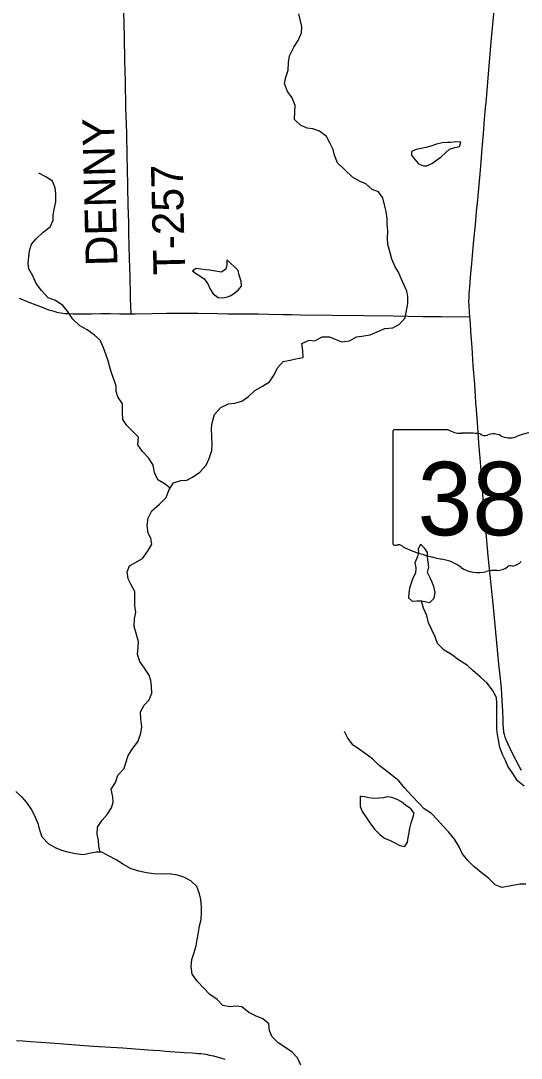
# Model space of a CAD drawing. Extents: x 1442749 to 1756758, y 235267 to 677782.
# Drawn here: x 1557097 to 1561837, y 528893 to 538726 of the extents above; entities that cross this region are included whole.
import ezdxf

# ---------------------------------------------------------------- set-up
doc = ezdxf.new("R2010")
doc.units = 0
for name, color, linetype in [('GM_X_County_Road', 7, 'Continuous'), ('GM_X_Minor_Lake', 7, 'Continuous'), ('GM_X_Minor_River', 7, 'Continuous'), ('GM_X_State_Location', 7, 'Continuous'), ('GM_X_State_Route', 7, 'Continuous'), ('GM_X_State_Shield', 7, 'Continuous'), ('GM_X_Township_Road', 7, 'Continuous'), ('GM_X_Township_Road_Text', 7, 'Continuous')]:
    doc.layers.add(name, color=color, linetype=linetype)

msp = doc.modelspace()

# ---------------------------------------------------------------- linework, layer by layer
at = {"layer": 'GM_X_County_Road'}
msp.add_lwpolyline([(1557056.5, 529060.7), (1557115.2, 529056.9), (1557189.4, 529052.1), (1557287.6, 529044.7), (1557376.8, 529037.8), (1557465.4, 529031.6), (1557656.3, 529017.7), (1557785.8, 529008.4), (1557948.9, 528998), (1558064.5, 528990.6), (1558181.6, 528982.5), (1558265.8, 528976.2), (1558301.4, 528973.2), (1558352, 528969.7), (1558413.1, 528965.2), (1558466.4, 528961.2), (1558556.9, 528954.9), (1558648.5, 528948.5), (1558721.2, 528943.4), (1558754.4, 528940.7), (1558777.5, 528938.8), (1558803.5, 528936.1), (1558829.4, 528933), (1558848.7, 528929.9), (1558884.3, 528923.4), (1558921.4, 528914.9), (1558953.8, 528905.9), (1558988.9, 528896.3), (1559030.3, 528884.3)], dxfattribs=at)
at = {"layer": 'GM_X_Minor_Lake'}
for points in [[(1561259.3, 537554.3), (1561266.6, 537574), (1561216.6, 537576.9), (1561170.5, 537571.9), (1561138.5, 537570.5), (1561088.5, 537569.5), (1561034.2, 537556.5), (1560979.8, 537537.6), (1560933.5, 537524.5), (1560889.3, 537515.3), (1560843.1, 537504.2), (1560798.7, 537487.1), (1560798, 537453), (1560818, 537426)], [(1560818, 537426), (1560864.3, 537369.6), (1560911.9, 537350.6), (1560942, 537352), (1560990.4, 537373.1), (1561079.8, 537437.4), (1561118.5, 537472.7), (1561159.3, 537510), (1561207.5, 537523), (1561251.8, 537534.2), (1561259.3, 537554.3)], [(1559080.3, 536118.9), (1559110.6, 536136.4), (1559157.4, 536171.5), (1559188.2, 536210.9), (1559183.1, 536257.1), (1559164.3, 536313.6), (1559155.2, 536357.8), (1559123.9, 536390.5), (1559084.6, 536429.3), (1559047.3, 536460.1), (1559048.3, 536412), (1559039.4, 536370.2), (1559007.5, 536349.8)], [(1559007.5, 536349.8), (1558996.8, 536343), (1558941, 536352.1), (1558889.2, 536363.1), (1558849.3, 536365.9), (1558803.4, 536372.8), (1558757.5, 536377.8), (1558725.1, 536356.3), (1558760.4, 536325.6), (1558794.1, 536306.9), (1558833.5, 536278.1), (1558868.6, 536233.3), (1558891.5, 536182.8), (1558918.6, 536136.2), (1558967.9, 536103.2), (1559009.9, 536100.3), (1559056.1, 536109.4), (1559080.3, 536118.9)], [(1560895.4, 533752.1), (1560884.6, 533763.3), (1560859.7, 533719.8), (1560862.8, 533677.6), (1560849.9, 533633.8), (1560829, 533588.2), (1560838, 533539.9), (1560835, 533489.9), (1560810, 533442.3), (1560795, 533394.5), (1560780.1, 533348.7), (1560771.1, 533302.8), (1560768.2, 533254.8), (1560805.6, 533226), (1560847.6, 533227.2), (1560893.6, 533226.3)], [(1560893.6, 533226.3), (1560971.3, 533212.7), (1561012.2, 533254), (1561021.3, 533305.9), (1561008.4, 533362.2), (1560991.4, 533410.6), (1560970.2, 533451.1), (1560949.1, 533495.6), (1560962.1, 533545.4), (1560955.2, 533595.7), (1560948.1, 533641.9), (1560949, 533685.9), (1560923.7, 533722.5), (1560895.4, 533752.1)], [(1560324.6, 531373.1), (1560311.7, 531374.6), (1560312.7, 531326.5), (1560311.7, 531278.4), (1560330.8, 531232), (1560365.8, 531181.2), (1560396.8, 531132.5), (1560420.2, 531102), (1560449.3, 531061.3), (1560496.4, 531012.3), (1560543.7, 530979.3), (1560597.2, 530956.2), (1560638.8, 530933.4), (1560686.3, 530910.4), (1560736.1, 530899.4), (1560761, 530941), (1560765.9, 530984.9)], [(1560765.9, 530984.9), (1560774.8, 531032.8), (1560781.7, 531074.8), (1560794.7, 531122.6), (1560811.7, 531172.3), (1560822.5, 531214.2), (1560791.4, 531256.9), (1560742.1, 531289.9), (1560702.7, 531322.8), (1560661.2, 531345.6), (1560611.6, 531364.7), (1560567.7, 531369.5), (1560533.5, 531362.2), (1560487.4, 531359.1), (1560441.3, 531354), (1560393.4, 531361), (1560351.6, 531369.8), (1560324.6, 531373.1)]]:
    msp.add_lwpolyline(points, dxfattribs=at)
at = {"layer": 'GM_X_Minor_River'}
for points in [[(1560762.6, 536113.6), (1560753.6, 536163.9), (1560728.8, 536220.5), (1560698.2, 536289.2), (1560673.2, 536341.8), (1560642.3, 536394.4), (1560611.7, 536465.2), (1560593.2, 536537.7), (1560572.6, 536606.2), (1560569.8, 536666.3), (1560575.2, 536732.3), (1560568.6, 536800.6), (1560567.7, 536852.7), (1560557, 536919), (1560546, 536969.3), (1560525.6, 537045.8), (1560486.8, 537104.7), (1560425.2, 537127.9), (1560366.3, 537179.2), (1560310.8, 537202.3), (1560239.5, 537241.8), (1560167, 537313.3), (1560098.3, 537378.8), (1560067.8, 537451.5), (1560054.9, 537505.8), (1560024.2, 537568.6), (1559993.4, 537629.3), (1559926.4, 537680.7), (1559862.8, 537700), (1559809, 537707), (1559745.5, 537736.3), (1559690.6, 537789.5), (1559694.1, 537863.6), (1559695.3, 537921.6), (1559666.8, 537994.3), (1559622, 538055.3), (1559595.6, 538131.9), (1559606.8, 538189.8), (1559628.2, 538257.5), (1559631.7, 538329.5), (1559641, 538393.4), (1559684.7, 538476.7), (1559725.9, 538538), (1559757.5, 538611.5), (1559758.7, 538671.6), (1559731.2, 538792.3)], [(1558511.6, 534297.1), (1558463.7, 534334.2), (1558396.5, 534373.6), (1558363.9, 534444.4), (1558351.3, 534512.8), (1558310.6, 534579.7), (1558249.9, 534643), (1558205.2, 534706), (1558212.7, 534777.9), (1558161.7, 534829), (1558100.9, 534888.3), (1558064.1, 534945.2), (1558061.6, 535019.3), (1558061.1, 535093.5), (1558016.4, 535160.5), (1557999.5, 535210.9), (1558000.5, 535260.9), (1557983.5, 535311.3), (1557955.1, 535390), (1557940.2, 535442.4), (1557925.4, 535502.8), (1557906.5, 535557.3), (1557881.9, 535625.9), (1557849.4, 535698.6), (1557794.4, 535745.8), (1557725.4, 535797.2), (1557656.1, 535832.7), (1557591.4, 535896.1), (1557541, 535973.2), (1557494, 536026.2), (1557427, 536073.6), (1557355.5, 536101.1), (1557294.9, 536168.4), (1557244.3, 536235.5), (1557211.7, 536308.2), (1557173.1, 536373.1), (1557168.1, 536425.3), (1557173.4, 536489.3), (1557178.6, 536545.3), (1557199.9, 536608.9), (1557242.9, 536660.2), (1557310.2, 536720.9), (1557375.3, 536771.8), (1557404.6, 536835.3), (1557403.6, 536885.4), (1557412.7, 536937.3), (1557430.1, 537009), (1557427.7, 537085.2), (1557422.9, 537143.4), (1557396.1, 537204), (1557333, 537247.3), (1557269.7, 537282.7)], [(1557850.3, 530845.8), (1557835.6, 530902.8), (1557834.7, 530958.9), (1557821.8, 531015.3), (1557825.2, 531081.3), (1557866.6, 531150.6), (1557915.7, 531201.7), (1557955, 531267.1), (1557972.1, 531318.8), (1557969.1, 531369), (1557952.5, 531441.4), (1557993.9, 531506.7), (1558015.3, 531576.4), (1558076.6, 531637.3), (1558093.7, 531691.1), (1558115.1, 531762.8), (1558154.4, 531824.1), (1558209.9, 531897.1), (1558233.5, 531974.8), (1558242.7, 532032.7), (1558234.2, 532109), (1558229.6, 532175.2), (1558266.9, 532238.6), (1558313.9, 532289.8), (1558337.2, 532351.4), (1558336.6, 532419.5), (1558329.7, 532473.8), (1558312.7, 532524.2), (1558268, 532589.2), (1558225.3, 532652.1), (1558202.7, 532720.7), (1558210.1, 532790.7), (1558213.1, 532840.7), (1558194.5, 532909.2), (1558170.1, 532985.8), (1558173.6, 533059.8), (1558186.8, 533117.7), (1558178.1, 533182), (1558177.4, 533248.1), (1558176.8, 533316.2), (1558140.2, 533385), (1558113.3, 533437.7), (1558104.6, 533502), (1558127.8, 533559.6), (1558178.4, 533588.6), (1558249.2, 533629.3), (1558302.8, 533704.4), (1558338, 533763.8), (1558329.1, 533818), (1558302.2, 533872.7), (1558295.6, 533942.9), (1558305.1, 534012.8), (1558338.5, 534082.3), (1558409.8, 534145), (1558475, 534205.8), (1558502.6, 534283.4), (1558543.9, 534346.7), (1558612.4, 534369.4), (1558670.5, 534372.2), (1558723.1, 534401.2), (1558794.1, 534447.9), (1558853.4, 534512.8), (1558880.8, 534578.4), (1558908.3, 534652), (1558911.4, 534708), (1558902.5, 534860.4), (1558909.7, 534916.4), (1558933.3, 534994), (1558992.6, 535061), (1559063.3, 535093.6), (1559125.5, 535102.4), (1559191.9, 535121.1), (1559252.8, 535166), (1559314, 535222.9), (1559386.9, 535263.5), (1559451.7, 535302.3), (1559497.1, 535369.5), (1559528.4, 535437), (1559581.7, 535496), (1559647.9, 535508.7), (1559702.2, 535521.7), (1559770.5, 535534.3), (1559769.8, 535598.4), (1559759.2, 535666.8), (1559829.8, 535697.4), (1559881.8, 535692.4), (1559950.5, 535729.1), (1560022.6, 535729.7), (1560074.1, 535708.6), (1560137.6, 535683.3), (1560209.8, 535691.9), (1560276.6, 535728.6), (1560328.7, 535735.6), (1560405, 535748.1), (1560473.6, 535776.8), (1560546.3, 535809.4), (1560620.4, 535813.9), (1560683.2, 535848.8), (1560736.4, 535909.8), (1560763.2, 536045.5), (1560762.6, 536113.6)], [(1561864, 531470.1), (1561803, 531521.3), (1561756.5, 531592.4), (1561711.8, 531659.4), (1561688.9, 531713.9), (1561661.9, 531764.6), (1561635.4, 531837.2), (1561622.9, 531909.6), (1561611.9, 531959.9), (1561605, 532012.1), (1561606, 532064.2), (1561605.4, 532130.3), (1561606.5, 532184.4), (1561606, 532256.5), (1561603.1, 532312.7), (1561566.5, 532381.5), (1561515.9, 532448.6), (1561451, 532504), (1561378.3, 532567.5), (1561327.2, 532614.7), (1561242.3, 532668.4), (1561177.3, 532717.8), (1561108.1, 532759.2), (1561043.4, 532822.6), (1561020.7, 532885.2), (1560990.1, 532953.9), (1560957.4, 533018.7), (1560942.8, 533089.1), (1560910.2, 533157.8), (1560893.6, 533226.3)], [(1561881.1, 530544.1), (1561827, 530541.2), (1561774.8, 530532.2), (1561724.7, 530523.2), (1561654.4, 530512.5), (1561588.9, 530535.9), (1561528.2, 530599.2), (1561459.2, 530652.6), (1561388.4, 530710.1), (1561331.5, 530767.4), (1561278.9, 530832.5), (1561248.2, 530897.2), (1561205.6, 530970.2), (1561149.1, 531039.4), (1561096.2, 531096.6), (1561045.3, 531151.7), (1560986.6, 531213), (1560917.4, 531256.4), (1560870.5, 531307.4), (1560801.9, 531380.9), (1560735.4, 531452.4), (1560678.8, 531521.6), (1560613.8, 531571), (1560542.9, 531628.5), (1560491.7, 531667.5), (1560427, 531728.9), (1560358, 531782.4), (1560304.7, 531817.5), (1560245.6, 531858.8), (1560194.9, 531925.9), (1560164.2, 531990.6)], [(1559749.7, 528827.2), (1559717.2, 528897.9), (1559668.2, 528951), (1559599.1, 528996.4), (1559534, 529037.8), (1559477.1, 529095), (1559454.3, 529151.6), (1559445.6, 529217.9), (1559388.6, 529267.1), (1559321.1, 529294.5), (1559255.8, 529325.8), (1559190.8, 529379.2), (1559139, 529386.2), (1559076.9, 529381.5), (1559011.1, 529392.8), (1558958.2, 529447.9), (1558887.1, 529495.4), (1558826.5, 529560.8), (1558769.6, 529620), (1558721, 529689.1), (1558710.5, 529761.4), (1558717.9, 529827.4), (1558739.2, 529895.1), (1558758.6, 529960.8), (1558767.7, 530016.7), (1558779.1, 530084.6), (1558790.4, 530146.5), (1558805.6, 530208.3), (1558809, 530276.4), (1558808, 530326.5), (1558803.5, 530396.7), (1558790.6, 530451.1), (1558766, 530519.7), (1558707.1, 530574.9), (1558641.7, 530608.3), (1558582.1, 530627.5), (1558502.3, 530639.1), (1558430.3, 530636.5), (1558358.4, 530642), (1558286.5, 530649.4), (1558216.8, 530664.8), (1558141.3, 530688.3), (1558070.1, 530729.8), (1558001, 530773.3), (1557933.6, 530806.7), (1557864.4, 530846.1), (1557812.4, 530845.1), (1557760.2, 530836.2), (1557687.9, 530821.6), (1557616, 530829), (1557544.3, 530846.4), (1557484.6, 530861.7), (1557433.1, 530882.7), (1557363.9, 530922.2), (1557299.2, 530987.5), (1557276.5, 531054.1), (1557263.6, 531108.5), (1557236.9, 531173.1), (1557200.4, 531248), (1557155.8, 531315), (1557110.8, 531365.9), (1557049.9, 531421.2)]]:
    msp.add_lwpolyline(points, dxfattribs=at)
at = {"layer": 'GM_X_State_Route'}
msp.add_lwpolyline([(1561840.7, 531623.6), (1561824.6, 531647.1), (1561751.3, 531787.4), (1561694.7, 531911.1), (1561685.1, 531936.9), (1561677.4, 531962), (1561672.9, 531979.9), (1561671.2, 531990.5), (1561668.8, 532017.8), (1561667, 532060.2), (1561664.9, 532110.6), (1561662, 532178.9), (1561657.7, 532283.7), (1561653.5, 532344.2), (1561648.8, 532401.6), (1561646, 532430.9), (1561637.1, 532521.3), (1561626.5, 532628.6), (1561603.8, 532865.5), (1561570.6, 533199.2), (1561552.1, 533380.8), (1561524, 533655.5), (1561497.4, 533943.7), (1561489.7, 534033.1), (1561473.9, 534237.7), (1561467.3, 534319.7), (1561456.2, 534461.5), (1561447, 534579.1), (1561436.1, 534723.2), (1561428.8, 534827.2), (1561419.5, 534958.3), (1561413.4, 535040), (1561408.4, 535108.1), (1561396.3, 535280.8), (1561383.4, 535458), (1561371.8, 535629.9), (1561366.5, 535703.5), (1561360.7, 535783.6), (1561355.5, 535856.4), (1561350.6, 535918.5), (1561347.4, 535963.6), (1561343, 536026.4), (1561342.3, 536064.7), (1561342.7, 536098.3), (1561344.3, 536138.7), (1561348.9, 536199.2), (1561358, 536295.4), (1561369.7, 536423.9), (1561383.2, 536577.6), (1561389.7, 536645.8), (1561400.7, 536763), (1561406.8, 536828.5), (1561414.4, 536916.7), (1561424.9, 537029.9), (1561434.6, 537134.4), (1561446.9, 537275.1), (1561456.7, 537387.2), (1561467.2, 537516.3), (1561482, 537693.8), (1561486.8, 537750.9), (1561497, 537865.8), (1561506.9, 537984.1), (1561520.3, 538144.4), (1561553.9, 538525.8), (1561565.8, 538654.5), (1561592.8, 538962.4)], dxfattribs=at)
at = {"layer": 'GM_X_State_Shield'}
for p, q in [((1560619.7, 534831.2), (1560619.7, 533774.5)), ((1561146.4, 534849.3), (1560636.8, 534849.3))]:
    msp.add_line(p, q, dxfattribs=at)
for centre, major_axis, start_param, end_param in [((1560639.6, 534833.4), (20.2, 0), 1.712693, 3.28349), ((1561267.8, 534972), (195.5, 0), 4.042523, 4.731795), ((1561332.6, 534256.1), (702, 0), 1.404758, 1.657858), ((1561975.4, 534526.6), (371.3, 0), 1.699011, 2.107814), ((1561492, 534838.9), (56.4, 0), 3.836095, 5.185415), ((1561574.8, 534716.8), (117.3, 0), 0.950623, 2.079405), ((1561726.2, 534884.3), (141.1, 0), 4.081561, 5.145723), ((1560639.8, 533772.2), (20.3, 0), 3.00124, 4.508301), ((1560642.9, 533880.3), (155.2, 0), 4.665946, 4.897461), ((1560674.6, 533713.6), (56, 0), 0.519207, 1.627899), ((1561381.2, 534662.9), (1332.7, 0), 4.195997, 4.488961), ((1560983.9, 533299.8), (417, 0), 0.823519, 1.323587), ((1561434.9, 533708.3), (264.6, 0), 4.026481, 4.996735), ((1561607.1, 533629.2), (141, 0), 4.691044, 5.507374), ((1561734.6, 533526.9), (39.7, 0), 1.147584, 2.315152), ((1561717.7, 533672.1), (149.1, 0), 4.937069, 5.64225), ((1561587.8, 533343), (217.4, 0), 1.495662, 1.94098)]:
    msp.add_ellipse(centre, major_axis=major_axis, ratio=0.8, start_param=start_param, end_param=end_param, dxfattribs=at)
at = {"layer": 'GM_X_Township_Road'}
for points in [[(1558142.8, 535949), (1558139.1, 536023.8), (1558136.9, 536090.6), (1558135.3, 536184.5), (1558134.2, 536235.6), (1558132.7, 536303.7), (1558128.2, 536471.2), (1558121.8, 536712), (1558119.1, 536810.4), (1558115.7, 536977.7), (1558107.4, 537328.7), (1558105.1, 537437), (1558100.4, 537663.3), (1558093.2, 537899.4), (1558087.7, 538152), (1558083.4, 538342.2), (1558078.5, 538573.3), (1558071, 538929.1), (1558063.3, 539588.9), (1558061, 539908.8), (1558057.3, 540179.4), (1558052.7, 540331.7)], [(1557082.6, 536096), (1557172.6, 536059.1), (1557240.7, 536033.2), (1557291.4, 536013.3), (1557332.6, 535997.2), (1557358.5, 535987.4), (1557387.6, 535978.3), (1557410.5, 535972), (1557440, 535964.8), (1557472, 535958.3), (1557496.2, 535954.7), (1557512.9, 535952.4), (1557535.2, 535950.8), (1557556.1, 535949.8), (1557594.9, 535948.9), (1557673.7, 535948.2), (1557765.6, 535948.8), (1557854.1, 535949.8), (1557942.7, 535949.6), (1558031.2, 535949.1), (1558126.2, 535948.9), (1558142.8, 535949)], [(1558142.8, 535949), (1558185.2, 535949.2), (1558341, 535951.6), (1558476.8, 535953.6), (1558613.1, 535954.1), (1558775, 535953.6), (1558958.1, 535950.6), (1559059.4, 535949.4), (1559149.5, 535948.7), (1559253.1, 535947.8), (1559348.2, 535946.6), (1559446.6, 535945.4), (1559580.8, 535942), (1559662.7, 535940.1), (1559748, 535938.4), (1560348.3, 535931.4), (1560623.9, 535927.7), (1560905.9, 535924.1), (1561078.4, 535922.1), (1561350.6, 535918.5)]]:
    msp.add_lwpolyline(points, dxfattribs=at)

# ---------------------------------------------------------------- texts
at = {"layer": 'GM_X_State_Location'}
for s in ['s', 'r']:
    msp.add_text(s, height=1, dxfattribs=at).set_placement((1561470.2, 534232.6))
msp.add_text('380', height=1, rotation=0.00001, dxfattribs=at).set_placement((1561117.2, 534159.8))
at = {"layer": 'GM_X_State_Shield'}
msp.add_text('380', height=696.1, dxfattribs=at).set_placement((1560855.9, 533849))
at = {"layer": 'GM_X_Township_Road_Text'}
for s, rotation, p in [('DENNY', 91.37301, (1558012.8, 536403.6)), ('T-257', 91.38439, (1558654.6, 536319))]:
    msp.add_text(s, height=300, rotation=rotation, dxfattribs=at).set_placement(p)

doc.saveas('drawing.dxf')
